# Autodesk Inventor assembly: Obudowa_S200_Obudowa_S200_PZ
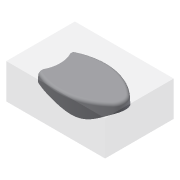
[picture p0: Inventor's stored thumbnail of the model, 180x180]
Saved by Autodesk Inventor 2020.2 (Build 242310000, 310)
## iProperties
Created: 2015-02
Part Number: Obudowa_S200_Obudowa_S200_PZ
Document SubType Name: Assembly
Designer: F.Stasiak
Catalog Web Link: www.expertbooks.pl
Manager: www.cadconsulting.pl
Company: Fabian Stasiak CAD Consulting
Author: F.Stasiak
Subject: Zbiór ćwiczeń. Autodesk Inventor 2020. Kurs Professional
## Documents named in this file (3)
- C:\2020_Kurs_Professional\R6 Formy\Komponenty\Obudowa_S200_Obudowa_S200_PZ.iam
- C:\2020_Kurs_Professional\R6 Formy\Komponenty\Obudowa_S200_Obudowa_S200_MP.ipt
- C:\2020_Kurs_Professional\R6 Formy\Komponenty\Obudowa_S200_Obudowa_S200_WP.ipt
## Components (2 placed, 2 different names)
1. Obudowa_S200_Obudowa_S200_MP:1 — Równoległy:1, Równoległy:2, Równoległy:3, Równoległy:4, Równoległy:5, Równoległy:6
2. Obudowa_S200_Obudowa_S200_WP:1 — Równoległy:4, Równoległy:5, Równoległy:6
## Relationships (6: Flush 6)
- Równoległy:1 [Flush]: Obudowa_S200_Obudowa_S200_MP:1
- Równoległy:2 [Flush]: Obudowa_S200_Obudowa_S200_MP:1
- Równoległy:3 [Flush]: Obudowa_S200_Obudowa_S200_MP:1
- Równoległy:4 [Flush]: Obudowa_S200_Obudowa_S200_MP:1 ↔ Obudowa_S200_Obudowa_S200_WP:1
- Równoległy:5 [Flush]: Obudowa_S200_Obudowa_S200_MP:1 ↔ Obudowa_S200_Obudowa_S200_WP:1
- Równoległy:6 [Flush]: Obudowa_S200_Obudowa_S200_MP:1 ↔ Obudowa_S200_Obudowa_S200_WP:1
